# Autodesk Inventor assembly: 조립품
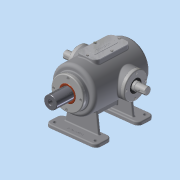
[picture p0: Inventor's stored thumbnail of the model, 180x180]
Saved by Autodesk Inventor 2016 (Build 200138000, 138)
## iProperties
Created: 2018-11
Part Number: 조립품
Material: 일반
Document SubType Name: Assembly
Designer: user
Author: user
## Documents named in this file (15)
- C:\Users\user\Desktop\381121V1008\381121V1008\조립품.iam
- C:\Users\user\Desktop\381121V1008\381121V1008\가변스프링.ipt
- C:\Users\user\Desktop\381121V1008\381121V1008\베어링 6205.ipt
- 베어링 6205.ipt
- C:\Users\user\Desktop\381121V1008\381121V1008\본체.ipt
- C:\Users\user\Desktop\381121V1008\381121V1008\볼트 M4x0.7.ipt
- C:\Users\user\Desktop\381121V1008\381121V1008\부시.ipt
- C:\Users\user\Desktop\381121V1008\381121V1008\상부커버.ipt
- C:\Users\user\Desktop\381121V1008\381121V1008\슬라이드 커버.ipt
- C:\Users\user\Desktop\381121V1008\381121V1008\슬라이드.ipt
- C:\Users\user\Desktop\381121V1008\381121V1008\오일실.ipt
- 오일실.ipt
- C:\Users\user\Desktop\381121V1008\381121V1008\육각머리볼트 M4.ipt
- C:\Users\user\Desktop\381121V1008\381121V1008\축 커버.ipt
- C:\Users\user\Desktop\381121V1008\381121V1008\편심축.ipt
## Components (13 placed, 2 different names)
1. 가변스프링:1
2. M4x0.7:2
3. M4x0.7:4
4. M4x0.7:5
5. M4x0.7:6
6. M4x0.7:1
7. M4x0.7:7
8. M4x0.7:8
9. M4x0.7:9
10. M4x0.7:3
11. M4x0.7:10
12. M4x0.7:11
13. M4x0.7:12
